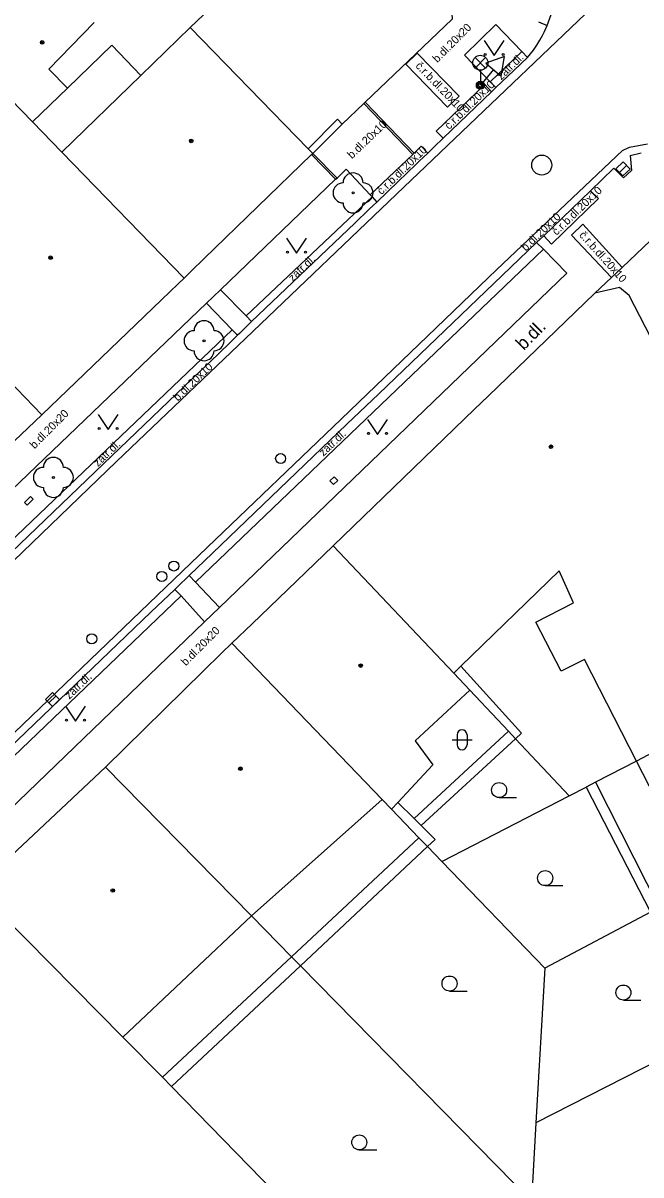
# Model space of a CAD drawing. Extents: x -596229 to -595156, y -1161237 to -1159376.
# Drawn here: x -596004.8 to -595973.9, y -1160640.7 to -1160583.1 of the extents above; entities that cross this region are included whole.
import ezdxf

# ---------------------------------------------------------------- set-up
doc = ezdxf.new("R2010")
doc.units = 0
for name, color, linetype in [('DOP - kresba z DSPS bez souradnic', 7, 'Continuous'), ('DOP - rozhrani ploch obecne', 7, 'Continuous'), ('Level 22', 7, 'Continuous'), ('Level 27', 7, 'Continuous'), ('Level 28', 7, 'Continuous'), ('Level 33', 7, 'Continuous'), ('Level 34', 7, 'Continuous'), ('Level 36', 7, 'Continuous'), ('Level 39', 7, 'Continuous'), ('silnoproud - povrch.  znaky a  RIS  skut. velikost', 7, 'Continuous'), ('TM - budovy zdene_ betonove - NP', 7, 'Continuous'), ('TM - budovy zdene_ betonove - VP', 7, 'Continuous'), ('TM - chodniky - VP', 7, 'Continuous'), ('TM - komunikace - VP', 7, 'Continuous'), ('TM - letecke snimky - pomocna linie', 7, 'Continuous'), ('TM - plot zdeny_ ohradni zed - VP', 7, 'Continuous'), ('TM - popis povrchu', 7, 'Continuous'), ('TM - rozhrani mezi zpev. plochami mezi sebou - VP', 7, 'Continuous'), ('TM - rozhrani ploch obecne - VP', 7, 'Continuous'), ('TM - vstup do budovy - zdene_ betonove', 7, 'Continuous'), ('TM - vstup do budovy - zdene_ betonove  - shora neviditelny', 7, 'Continuous')]:
    doc.layers.add(name, color=color, linetype=linetype)

msp = doc.modelspace()

# ---------------------------------------------------------------- linework, layer by layer
at = {"layer": 'DOP - kresba z DSPS bez souradnic'}
for points in [[(-595979.92, -1160618.63), (-595982.94, -1160615.28)], [(-595985.28, -1160622.9), (-595980.56, -1160618.54)], [(-595984.93, -1160623.25), (-595980.22, -1160618.91)], [(-595980.22, -1160618.91), (-595979.92, -1160618.63)], [(-595976.22, -1160621.09), (-595973.03, -1160627.36)], [(-595986.09, -1160622.1), (-595985.28, -1160622.9)], [(-595985.28, -1160622.9), (-595984.93, -1160623.25)], [(-595984.23, -1160623.95), (-595984.93, -1160623.25)], [(-595985.04, -1160623.86), (-595991.4, -1160629.81)], [(-595984.61, -1160624.3), (-595984.23, -1160623.95)], [(-595991.4, -1160629.81), (-595997.85, -1160635.83)]]:
    msp.add_lwpolyline(points, dxfattribs=at)
at = {"layer": 'DOP - rozhrani ploch obecne'}
for points in [[(-595982.49, -1160616.48), (-595980.56, -1160618.54)], [(-595980.56, -1160618.54), (-595980.22, -1160618.91)], [(-595980.22, -1160618.91), (-595977.53, -1160621.77)], [(-595974.17, -1160620.03), (-595976.22, -1160621.09)], [(-595976.22, -1160621.09), (-595976.68, -1160621.33)], [(-595983.89, -1160625.05), (-595977.53, -1160621.77)], [(-595977.53, -1160621.77), (-595976.68, -1160621.33)], [(-595976.68, -1160621.33), (-595973.46, -1160627.59)], [(-595985.04, -1160623.86), (-595986.41, -1160622.44)], [(-595984.61, -1160624.3), (-595985.04, -1160623.86)], [(-595984.61, -1160624.3), (-595990.96, -1160630.26)], [(-595983.89, -1160625.05), (-595984.61, -1160624.3)], [(-595978.75, -1160630.38), (-595983.89, -1160625.05)], [(-595993.4, -1160627.77), (-595991.4, -1160629.81)], [(-595973.46, -1160627.59), (-595978.75, -1160630.38)], [(-595991.4, -1160629.81), (-595990.96, -1160630.26)], [(-595990.96, -1160630.26), (-595997.4, -1160636.3)], [(-595979.42, -1160642.02), (-595990.96, -1160630.26)], [(-595978.75, -1160630.38), (-595979.19, -1160638.12)], [(-595999.84, -1160633.83), (-595997.85, -1160635.83)], [(-595970.36, -1160633.61), (-595979.19, -1160638.12)], [(-595997.85, -1160635.83), (-595997.4, -1160636.3)], [(-595997.4, -1160636.3), (-595985.14, -1160648.88)], [(-595979.19, -1160638.12), (-595979.42, -1160642.02)]]:
    msp.add_lwpolyline(points, dxfattribs=at)
at = {"layer": 'Level 22'}
for centre in [(-595988.33, -1160591.63), (-595995.78, -1160599.02), (-596003.31, -1160605.85)]:
    msp.add_circle(centre, 0.05, dxfattribs=at)
for centre, start, end in [((-595988.33, -1160591.13), 0, 180), ((-595988.83, -1160591.63), 90, 270), ((-595987.83, -1160591.63), 270, 90), ((-595988.33, -1160592.13), 180, 0), ((-595995.78, -1160598.52), 0, 180), ((-595996.28, -1160599.02), 90, 270), ((-595995.28, -1160599.02), 270, 90), ((-595995.78, -1160599.52), 180, 0), ((-596003.31, -1160605.35), 0, 180), ((-596003.81, -1160605.85), 90, 270), ((-596002.81, -1160605.85), 270, 90), ((-596003.31, -1160606.35), 180, 0)]:
    msp.add_arc(centre, 0.5, start, end, dxfattribs=at)
at = {"layer": 'Level 27'}
for p, q in [((-595975.02, -1160590.603), (-595974.66, -1160590.257)), ((-596003.529, -1160617.125), (-596003.171, -1160616.775))]:
    msp.add_line(p, q, dxfattribs=at)
for points in [[(-595974.847, -1160590.783), (-595974.487, -1160590.437), (-595974.833, -1160590.077), (-595975.193, -1160590.423)], [(-596003.354, -1160617.304), (-596002.996, -1160616.954), (-596003.346, -1160616.596), (-596003.704, -1160616.946)]]:
    msp.add_lwpolyline(points, close=True, dxfattribs=at)
msp.add_circle((-595978.9, -1160590.24), 0.5, dxfattribs=at)
at = {"layer": 'Level 28'}
for centre in [(-595991.95, -1160604.91), (-595997.29, -1160610.28), (-595997.89, -1160610.8), (-596001.39, -1160613.92)]:
    msp.add_circle(centre, 0.25, dxfattribs=at)
at = {"layer": 'Level 33'}
for p, q in [((-595982.235, -1160585.39), (-595981.705, -1160584.86)), ((-595982.235, -1160584.86), (-595981.705, -1160585.39)), ((-595981.97, -1160585.5), (-595981.97, -1160586.25))]:
    msp.add_line(p, q, dxfattribs=at)
for centre, radius in [((-595981.97, -1160585.125), 0.375), ((-595981.97, -1160586.25), 0.2), ((-595981.97, -1160586.25), 0.145), ((-595981.97, -1160586.25), 0.0876)]:
    msp.add_circle(centre, radius, dxfattribs=at)
at = {"layer": 'Level 34'}
msp.add_line((-595981.316, -1160585.47), (-595981.97, -1160586.25), dxfattribs=at)
msp.add_lwpolyline([(-595981.699, -1160585.149), (-595980.933, -1160585.792), (-595980.759, -1160584.807)], close=True, dxfattribs=at)
at = {"layer": 'Level 36'}
for p, q in [((-595983.136, -1160618.716), (-595983.136, -1160619.216)), ((-595982.636, -1160618.716), (-595982.636, -1160619.216)), ((-595983.386, -1160618.966), (-595982.386, -1160618.966)), ((-595981.03, -1160621.855), (-595980.155, -1160621.855)), ((-595978.73, -1160626.255), (-595977.855, -1160626.255)), ((-595983.51, -1160631.525), (-595982.635, -1160631.525)), ((-595974.82, -1160631.975), (-595973.945, -1160631.975)), ((-595988.02, -1160639.465), (-595987.145, -1160639.465))]:
    msp.add_line(p, q, dxfattribs=at)
for points in [[(-595981.78, -1160584.01), (-595981.28, -1160584.76), (-595980.78, -1160584.01)], [(-595991.66, -1160593.89), (-595991.16, -1160594.64), (-595990.66, -1160593.89)], [(-596001.07, -1160602.71), (-596000.57, -1160603.46), (-596000.07, -1160602.71)], [(-595987.61, -1160602.95), (-595987.11, -1160603.7), (-595986.61, -1160602.95)], [(-596002.7, -1160617.28), (-596002.2, -1160618.03), (-596001.7, -1160617.28)]]:
    msp.add_lwpolyline(points, dxfattribs=at)
for centre, radius in [((-595981.73, -1160584.71), 0.05), ((-595980.831, -1160584.71), 0.05), ((-595991.61, -1160594.59), 0.05), ((-595990.711, -1160594.59), 0.05), ((-596001.02, -1160603.41), 0.05), ((-596000.121, -1160603.41), 0.05), ((-595987.56, -1160603.65), 0.05), ((-595986.661, -1160603.65), 0.05), ((-596002.65, -1160617.98), 0.05), ((-596001.751, -1160617.98), 0.05), ((-595981.03, -1160621.48), 0.375), ((-595978.73, -1160625.88), 0.375), ((-595983.51, -1160631.15), 0.375), ((-595974.82, -1160631.6), 0.375), ((-595988.02, -1160639.09), 0.375)]:
    msp.add_circle(centre, radius, dxfattribs=at)
for centre, start, end in [((-595982.886, -1160618.716), 0, 180), ((-595982.886, -1160619.216), 180, 0)]:
    msp.add_arc(centre, 0.25, start, end, dxfattribs=at)
at = {"layer": 'Level 39'}
for centre, radius in [((-596003.87, -1160584.11), 0.09), ((-596003.87, -1160584.11), 0.0398), ((-595996.42, -1160589.03), 0.09), ((-595996.42, -1160589.03), 0.0398), ((-596003.45, -1160594.87), 0.09), ((-596003.45, -1160594.87), 0.0398), ((-595978.44, -1160604.32), 0.09), ((-595978.44, -1160604.32), 0.0398), ((-595987.95, -1160615.26), 0.09), ((-595987.95, -1160615.26), 0.0398), ((-595993.96, -1160620.41), 0.09), ((-595993.96, -1160620.41), 0.0398), ((-596000.34, -1160626.5), 0.09), ((-596000.34, -1160626.5), 0.0398)]:
    msp.add_circle(centre, radius, dxfattribs=at)
at = {"layer": 'silnoproud - povrch.  znaky a  RIS  skut. velikost'}
for points in [[(-595989.31, -1160606.21), (-595989.49, -1160606.02), (-595989.28, -1160605.82), (-595989.1, -1160606.01)], [(-595989.1, -1160606.01), (-595989.31, -1160606.21)], [(-596004.62, -1160607.24), (-596004.75, -1160607.11), (-596004.45, -1160606.81), (-596004.32, -1160606.94)], [(-596004.62, -1160607.24), (-596004.32, -1160606.94)]]:
    msp.add_lwpolyline(points, dxfattribs=at)
at = {"layer": 'TM - budovy zdene_ betonove - NP'}
msp.add_lwpolyline([(-595989.11, -1160587.95), (-595988.87, -1160588.19)], dxfattribs=at)
at = {"layer": 'TM - budovy zdene_ betonove - VP'}
for points in [[(-595994.82, -1160581.78), (-595996.47, -1160583.37)], [(-595983.42, -1160582.12), (-595983.38, -1160582.94), (-595987.72, -1160587.09)], [(-596001.27, -1160583.11), (-596003.53, -1160585.44)], [(-595998.93, -1160585.76), (-595996.47, -1160583.37)], [(-595996.47, -1160583.37), (-595990.58, -1160589.42)], [(-596002.61, -1160586.39), (-596000.39, -1160584.25)], [(-596000.39, -1160584.25), (-595998.93, -1160585.76)], [(-596004.36, -1160588.08), (-596007.06, -1160585.3)], [(-596003.53, -1160585.44), (-596002.61, -1160586.39)], [(-596002.61, -1160586.39), (-596004.36, -1160588.08)], [(-595987.79, -1160587.16), (-595988.87, -1160588.19)], [(-595987.72, -1160587.09), (-595987.79, -1160587.16)], [(-596002.89, -1160589.6), (-596004.36, -1160588.08)], [(-595990.34, -1160589.66), (-595988.87, -1160588.19)], [(-595990.34, -1160589.66), (-595990.58, -1160589.42)], [(-595996.78, -1160595.9), (-596002.89, -1160589.6)], [(-595995.77, -1160594.91), (-595990.4, -1160589.71)], [(-595990.4, -1160589.71), (-595990.34, -1160589.66)], [(-596003.89, -1160602.73), (-596010.56, -1160595.8)], [(-595996.78, -1160595.9), (-595997.08, -1160596.18)], [(-595996.42, -1160595.55), (-595996.78, -1160595.9)], [(-595975.01, -1160596.36), (-595976.24, -1160596.64)], [(-595974.54, -1160596.76), (-595975.01, -1160596.36)], [(-595997.91, -1160596.98), (-596003.89, -1160602.73)], [(-595981.58, -1160601.79), (-595976.24, -1160596.64)], [(-595973.19, -1160599.37), (-595974.54, -1160596.76)], [(-596003.89, -1160602.73), (-596009.75, -1160608.29)], [(-595989.32, -1160609.27), (-595982.26, -1160602.44)], [(-595992.51, -1160612.33), (-595989.32, -1160609.27)], [(-595989.32, -1160609.27), (-595983.3, -1160615.63)], [(-595978.03, -1160610.52), (-595982.94, -1160615.28)], [(-595977.31, -1160612.12), (-595978.03, -1160610.52)], [(-595979.19, -1160613.08), (-595977.31, -1160612.12)], [(-595994.39, -1160614.14), (-595993.38, -1160613.17)], [(-595977.93, -1160615.54), (-595979.19, -1160613.08)], [(-595994.9, -1160614.64), (-595994.39, -1160614.14)], [(-595986.88, -1160621.95), (-595994.39, -1160614.14)], [(-595982.94, -1160615.28), (-595983.3, -1160615.63)], [(-595976.77, -1160614.96), (-595977.93, -1160615.54)], [(-595974.17, -1160620.03), (-595976.77, -1160614.96)], [(-595964.96, -1160615.15), (-595974.17, -1160620.03)], [(-596000.7, -1160620.33), (-595995.82, -1160615.54)], [(-595983.3, -1160615.63), (-595982.49, -1160616.48)], [(-595982.49, -1160616.48), (-595985.23, -1160619.02)], [(-595985.23, -1160619.02), (-595984.34, -1160620.21)], [(-595970.97, -1160626.27), (-595974.17, -1160620.03)], [(-596005.68, -1160625.02), (-596000.7, -1160620.33)], [(-596000.7, -1160620.33), (-595993.4, -1160627.77)], [(-595984.34, -1160620.21), (-595986.09, -1160622.1)], [(-595986.88, -1160621.95), (-595993.4, -1160627.77)], [(-595986.41, -1160622.44), (-595986.88, -1160621.95)], [(-595986.09, -1160622.1), (-595986.41, -1160622.44)], [(-595999.84, -1160633.83), (-596007.11, -1160626.47)], [(-595993.4, -1160627.77), (-595999.84, -1160633.83)]]:
    msp.add_lwpolyline(points, dxfattribs=at)
at = {"layer": 'TM - chodniky - VP'}
for points in [[(-595982.76, -1160584.74), (-595981.19, -1160583.21)], [(-595979.9, -1160584.57), (-595981.19, -1160583.21)], [(-595981.48, -1160586.08), (-595982.76, -1160584.74)], [(-595981.48, -1160586.08), (-595979.9, -1160584.57)], [(-595989.13, -1160590.89), (-595988.67, -1160590.44), (-595987.48, -1160591.72)], [(-595994.95, -1160596.47), (-595989.21, -1160590.95)], [(-595989.21, -1160590.95), (-595989.13, -1160590.89)], [(-595993.68, -1160597.78), (-595987.38, -1160591.83)], [(-595987.48, -1160591.72), (-595987.38, -1160591.83)], [(-595996.2, -1160611.08), (-595978.81, -1160594.44)], [(-595978.81, -1160594.44), (-595977.64, -1160595.65)], [(-595995, -1160612.35), (-595977.64, -1160595.65)], [(-595993.68, -1160597.78), (-595994.95, -1160596.47)], [(-596008.65, -1160609.59), (-595995.65, -1160597.14)], [(-595995.65, -1160597.14), (-595994.37, -1160598.47)], [(-596007.38, -1160610.89), (-595994.37, -1160598.47)], [(-595996.2, -1160611.08), (-595995, -1160612.35)], [(-596008.12, -1160622.49), (-595996.93, -1160611.77)], [(-595996.93, -1160611.77), (-595995.75, -1160613.07)], [(-596006.92, -1160623.81), (-595995.75, -1160613.07)]]:
    msp.add_lwpolyline(points, dxfattribs=at)
at = {"layer": 'TM - komunikace - VP'}
for points in [[(-595978.63, -1160583.26), (-595978.43, -1160582.72), (-595978.34, -1160582.36), (-595978.27, -1160582), (-595978.23, -1160581.78), (-595978.2, -1160581.36), (-595978.2, -1160581.22), (-595978.2, -1160581.07), (-595978.2, -1160580.86), (-595978.21, -1160580.46), (-595978.29, -1160579.95), (-595978.53, -1160579.09), (-595978.72, -1160578.65), (-595979.07, -1160578.13)], [(-595979.62, -1160584.86), (-595979.31, -1160584.49), (-595979.15, -1160584.25), (-595978.99, -1160583.99), (-595978.86, -1160583.77), (-595978.76, -1160583.57), (-595978.63, -1160583.26)], [(-595979.62, -1160584.86), (-595980.29, -1160585.51), (-595981.19, -1160586.37)], [(-595981.41, -1160586.58), (-595983.82, -1160588.9)], [(-595981.19, -1160586.37), (-595981.41, -1160586.58)], [(-595983.82, -1160588.9), (-595984.27, -1160589.33), (-595984.6, -1160589.64)], [(-595984.6, -1160589.64), (-595985.03, -1160590.05), (-595985.18, -1160590.19), (-595986.07, -1160591.06)], [(-595974.48, -1160589.76), (-595974.41, -1160590.51), (-595974.81, -1160590.88), (-595975.29, -1160590.4), (-595976.46, -1160591.52)], [(-595974.48, -1160589.76), (-595973.94, -1160589.63)], [(-595986.07, -1160591.06), (-595987.15, -1160592.09)], [(-595976.46, -1160591.52), (-595978.8, -1160593.77)], [(-595987.15, -1160592.09), (-595987.33, -1160592.26), (-595987.53, -1160592.45), (-595988.25, -1160593.14), (-595993.4, -1160598.06)], [(-595979.16, -1160594.11), (-595980.88, -1160595.76), (-595987.05, -1160601.67), (-595988.64, -1160603.19), (-595995.35, -1160609.63), (-595996.52, -1160610.75)], [(-595978.8, -1160593.77), (-595979.16, -1160594.11)], [(-595993.4, -1160598.06), (-595994.01, -1160598.65), (-595994.11, -1160598.74)], [(-595994.11, -1160598.74), (-595994.52, -1160599.15), (-595995.48, -1160600.07), (-595995.94, -1160600.51), (-596000.39, -1160604.77), (-596007.09, -1160611.18)], [(-595996.52, -1160610.75), (-595997.11, -1160611.32), (-595997.24, -1160611.45)], [(-595997.24, -1160611.45), (-595998.42, -1160612.57), (-596008.45, -1160622.18)]]:
    msp.add_lwpolyline(points, dxfattribs=at)
at = {"layer": 'TM - letecke snimky - pomocna linie'}
for points in [[(-595995.65, -1160597.14), (-595994.95, -1160596.47)], [(-595995.75, -1160613.07), (-595995, -1160612.35)]]:
    msp.add_lwpolyline(points, dxfattribs=at)
at = {"layer": 'TM - plot zdeny_ ohradni zed - VP'}
for points in [[(-595974.89, -1160595.36), (-595972.42, -1160593.01), (-595972.01, -1160592.9)], [(-595976.24, -1160596.64), (-595975.42, -1160595.86)], [(-595975.42, -1160595.86), (-595974.89, -1160595.36)]]:
    msp.add_lwpolyline(points, dxfattribs=at)
at = {"layer": 'TM - rozhrani mezi zpev. plochami mezi sebou - VP'}
for points in [[(-595973.81, -1160579.89), (-595985.8, -1160591.35), (-595993.71, -1160598.9)], [(-595979.07, -1160583.08), (-595978.63, -1160583.26)], [(-595985.7, -1160585.19), (-595985.13, -1160584.64)], [(-595985.13, -1160584.64), (-595983.03, -1160586.8), (-595983.61, -1160587.35)], [(-595979.62, -1160584.86), (-595979.9, -1160584.57)], [(-595983.61, -1160587.35), (-595985.7, -1160585.19)], [(-595981.19, -1160586.37), (-595981.48, -1160586.08)], [(-595983.82, -1160588.9), (-595984.18, -1160588.55), (-595981.75, -1160586.21), (-595981.41, -1160586.58)], [(-595987.79, -1160587.16), (-595986.56, -1160588.44), (-595985.35, -1160589.71)], [(-595987.72, -1160587.09), (-595985.28, -1160589.64)], [(-595974.87, -1160589.51), (-595981.14, -1160595.46), (-595988.93, -1160602.94)], [(-595985.28, -1160589.64), (-595984.93, -1160589.3)], [(-595984.6, -1160589.64), (-595984.93, -1160589.3)], [(-595974.87, -1160589.51), (-595974.52, -1160589.35)], [(-595974.52, -1160589.35), (-595973.62, -1160589.17)], [(-595990.4, -1160589.71), (-595989.21, -1160590.95)], [(-595990.34, -1160589.66), (-595989.13, -1160590.89)], [(-595987.48, -1160591.72), (-595985.35, -1160589.71)], [(-595985.35, -1160589.71), (-595985.28, -1160589.64)], [(-595987.38, -1160591.83), (-595987.15, -1160592.09)], [(-595976.46, -1160591.52), (-595976.06, -1160591.91), (-595978.41, -1160594.2), (-595978.8, -1160593.77)], [(-595975.42, -1160595.86), (-595977.42, -1160593.75), (-595976.85, -1160593.2), (-595974.89, -1160595.36)], [(-595979.16, -1160594.11), (-595978.81, -1160594.44)], [(-595993.4, -1160598.06), (-595993.68, -1160597.78)], [(-595994.37, -1160598.47), (-595994.11, -1160598.74)], [(-595993.71, -1160598.9), (-596000.15, -1160605.06), (-596008.14, -1160612.73), (-596014.69, -1160618.96), (-596028.33, -1160632.06), (-596042.1, -1160645.23), (-596054.28, -1160656.88), (-596054.86, -1160657.4)], [(-595988.93, -1160602.94), (-595995.6, -1160609.34), (-596010.29, -1160623.41), (-596023.98, -1160636.45), (-596037.8, -1160649.75), (-596045.64, -1160657.26)], [(-595996.52, -1160610.75), (-595996.2, -1160611.08)], [(-595997.24, -1160611.45), (-595996.93, -1160611.77)]]:
    msp.add_lwpolyline(points, dxfattribs=at)
at = {"layer": 'TM - rozhrani ploch obecne - VP'}
msp.add_lwpolyline([(-596002.89, -1160589.6), (-595998.93, -1160585.76)], dxfattribs=at)
at = {"layer": 'TM - vstup do budovy - zdene_ betonove'}
for points in [[(-595996.42, -1160595.55), (-595995.77, -1160594.91)], [(-595997.91, -1160596.98), (-595997.08, -1160596.18)], [(-595981.58, -1160601.79), (-595982.26, -1160602.44)], [(-595992.51, -1160612.33), (-595993.38, -1160613.17)], [(-595994.9, -1160614.64), (-595995.82, -1160615.54)]]:
    msp.add_lwpolyline(points, dxfattribs=at)
at = {"layer": 'TM - vstup do budovy - zdene_ betonove  - shora neviditelny'}
msp.add_lwpolyline([(-595990.58, -1160589.42), (-595989.11, -1160587.95)], dxfattribs=at)

# ---------------------------------------------------------------- texts
at = {"layer": 'TM - popis povrchu'}
for s, height, rotation, p in [('b.dl.20x20', 0.4, 45.25568, (-595984.12, -1160585.15)), ('zatr.dl.', 0.4, 44, (-595980.92, -1160586.01)), ('č.r.b.dl.20x10', 0.4, 314, (-595985.24, -1160585.31)), ('č.r.b.dl.20x10', 0.4, 44, (-595983.53, -1160588.49)), ('b.dl.20x10', 0.4, 43.60296, (-595988.39, -1160589.95)), ('č.r.b.dl.20x10', 0.4, 44, (-595986.91, -1160591.75)), ('č.r.b.dl.20x10', 0.4, 44, (-595978.16, -1160593.78)), ('b.dl.20x10', 0.4, 43.69806, (-595979.7, -1160594.57)), ('č.r.b.dl.20x10', 0.4, 312, (-595977.06, -1160593.76)), ('zatr.dl.', 0.4, 43.60296, (-595991.34, -1160596.09)), ('b.dl.', 0.65, 45.44, (-595979.8, -1160599.53)), ('b.dl.20x10', 0.4, 43.69806, (-595997.09, -1160602.07)), ('b.dl.20x20', 0.4, 45.25568, (-596004.25, -1160604.45)), ('zatr.dl.', 0.4, 43.60296, (-595989.81, -1160604.82)), ('zatr.dl.', 0.4, 43.60296, (-596001.08, -1160605.34)), ('b.dl.20x20', 0.4, 45.25568, (-595996.69, -1160615.3)), ('zatr.dl.', 0.4, 43.60296, (-596002.51, -1160616.96))]:
    msp.add_text(s, height=height, rotation=rotation, dxfattribs=at).set_placement(p)

doc.saveas('drawing.dxf')
